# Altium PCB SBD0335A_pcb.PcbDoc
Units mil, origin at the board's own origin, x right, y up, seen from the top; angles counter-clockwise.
Board outline 1150 x 1150 mil, 2 copper layers (Top Layer, Bottom Layer), stack 64.8 mil thick; 36 components, 19 nets, 72 pads, 19 vias.
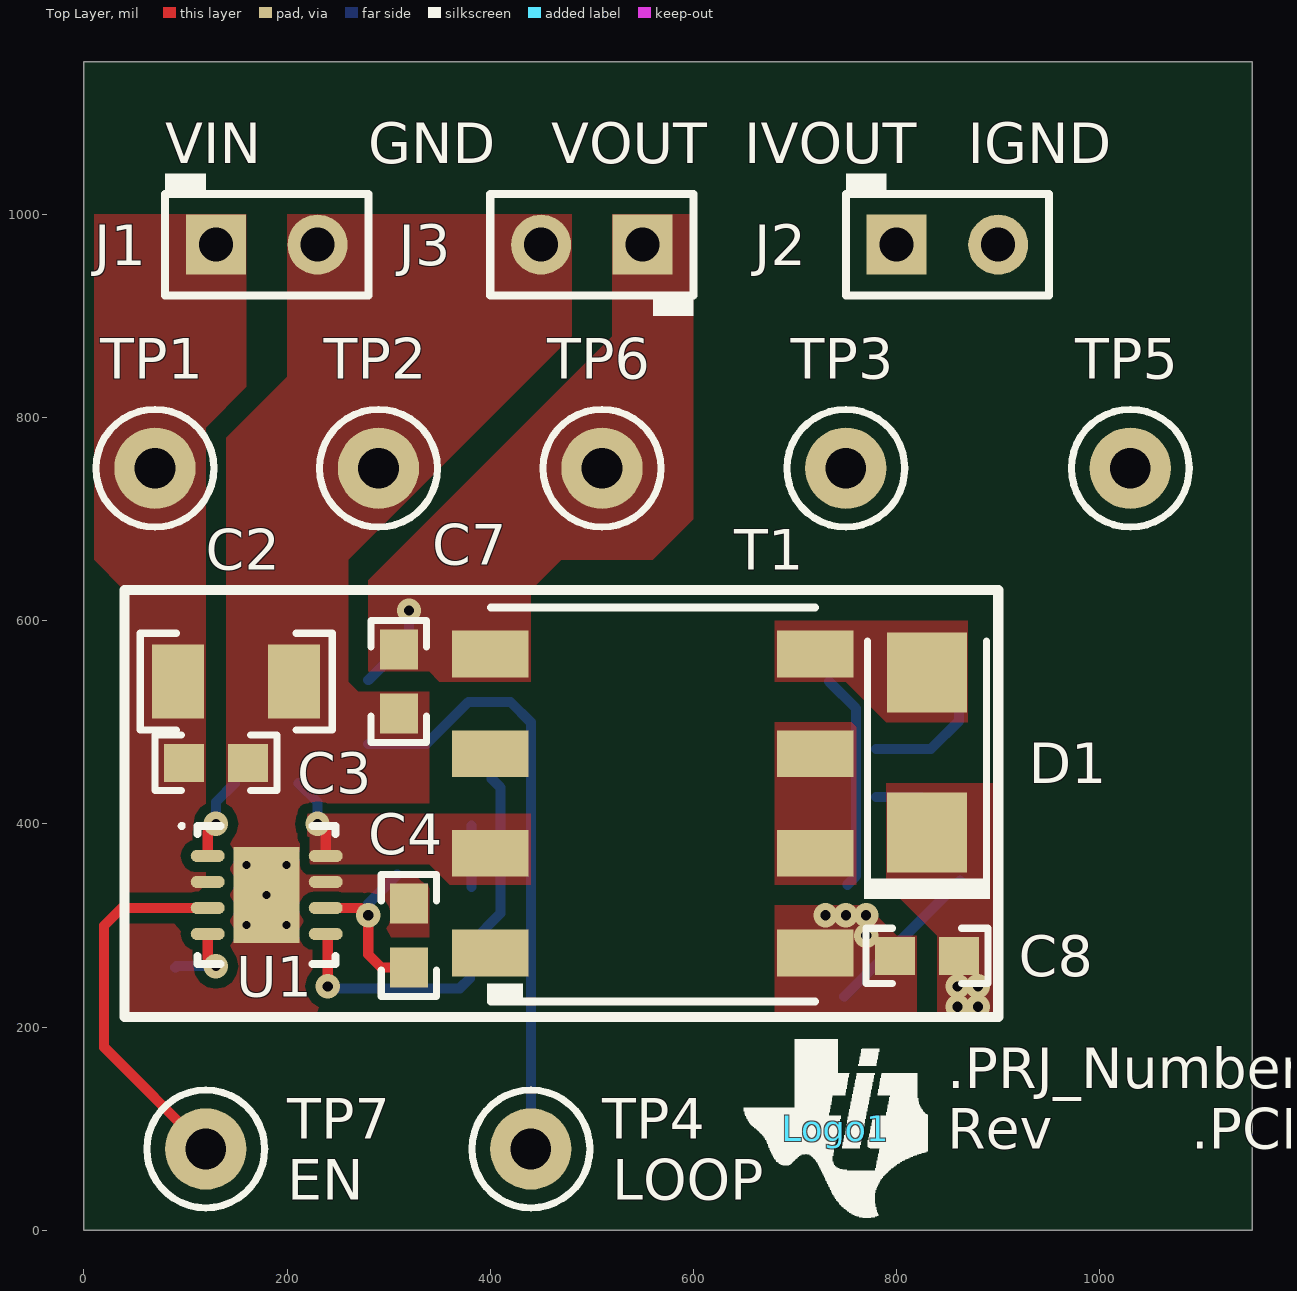
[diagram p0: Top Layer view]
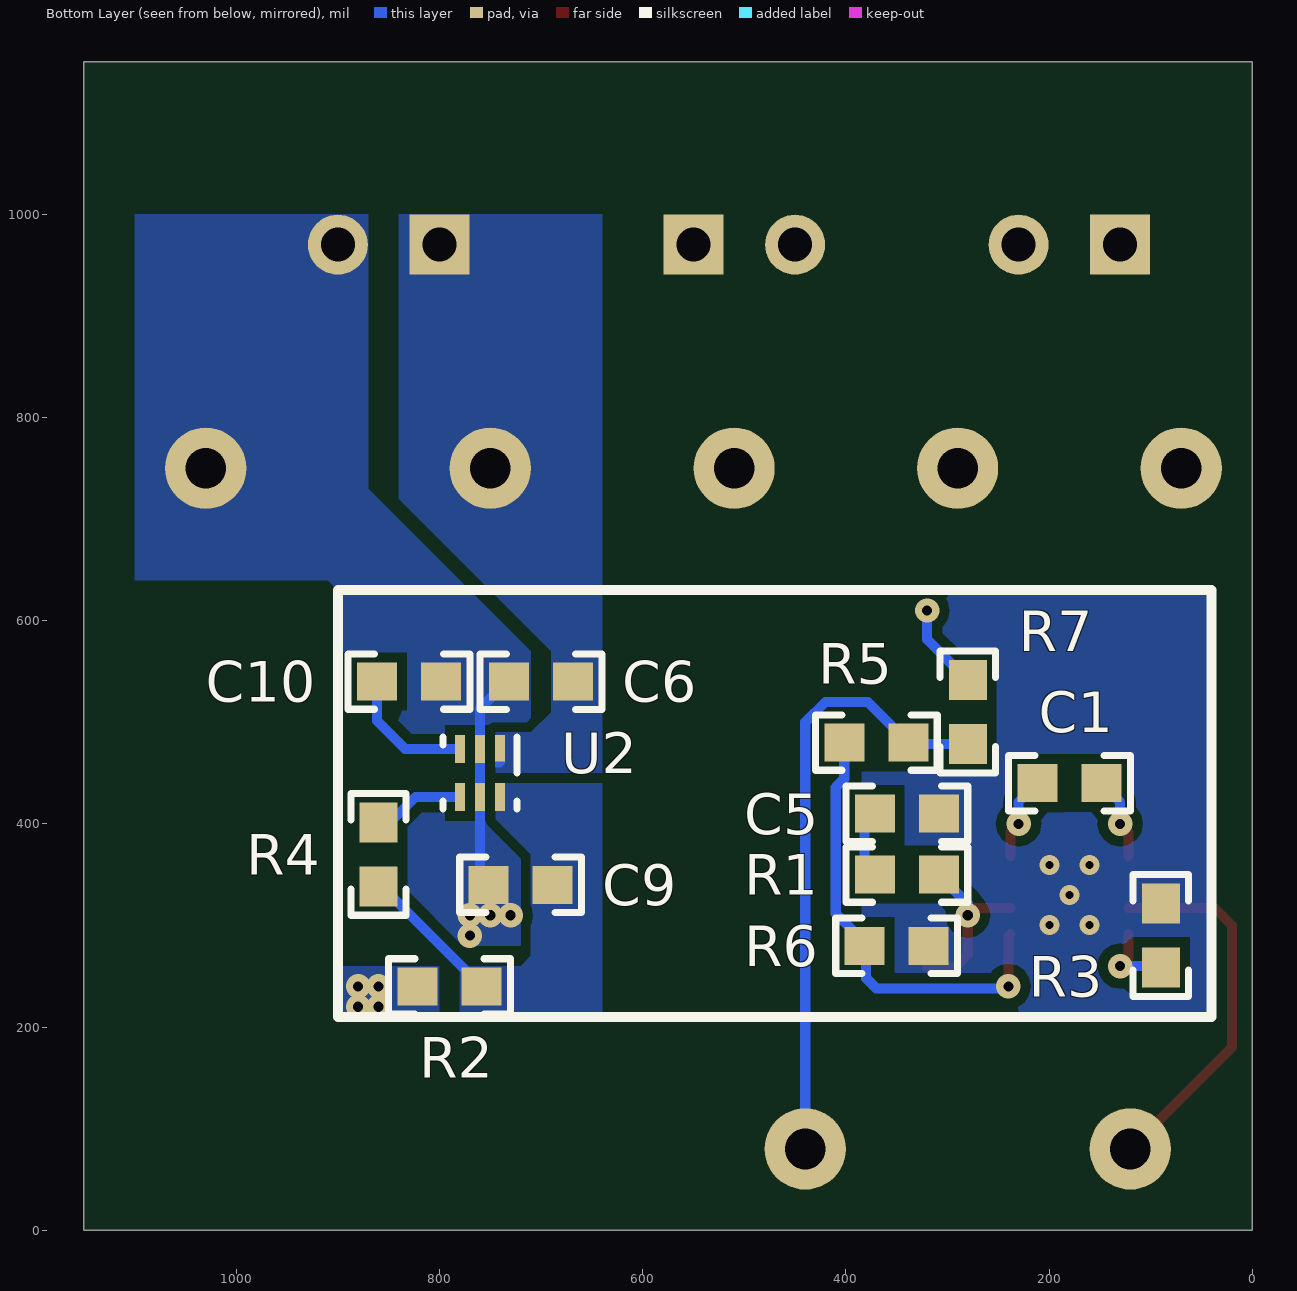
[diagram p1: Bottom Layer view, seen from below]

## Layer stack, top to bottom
Top Solder: solder mask 0.4, Solder Resist, Dk 3.5
Top Layer: signal copper 2.8
Dielectric1: core 59.2, FR-4, Dk 4.8
Bottom Layer: signal copper 2.8
Bottom Solder: solder mask 0.4, Solder Resist, Dk 3.5

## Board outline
0,0 0,1150 1150,1150 1150,0

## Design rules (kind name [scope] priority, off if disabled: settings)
AcuteAngle [All] p1: minimum=4.50000000000000E+0001 checktracksonly=FALSE
AssemblyTestPointUsage [All] p1: valid=2
Clearance Clearance_BoardEdge_MountingHoles [OnCopper and InComponentClass('Mounting Holes') vs IsKeepOut] p1: gap=40
Clearance Clearance_BoardEdge_Poly [OnCopper and InPoly vs IsKeepOut] p2: gap=25
Clearance Clearance_BoardEdge [OnCopper and Not InComponentClass('Logo') and not InComponentClass('FiducialMark') and not InRegion(1000,500,4000,800) and Not IsKeepout vs IsKeepOut] p3: gap=75
Clearance Clearance_Poly [InPolygon] p4: gap=10
Clearance [All] p5: gap=8
ComponentClearance ComponentClearance_Shunt [InComponentClass('Header') vs InComponentClass('Shunt')] p1: gap=0 collisioncheckmode=3 verticalgap=0 showdistances=FALSE
ComponentClearance ComponentClearance_Logo [InComponentClass('Logo')] p2: gap=50 collisioncheckmode=3 verticalgap=10 showdistances=FALSE
ComponentClearance ComponentClearance_ScrewToNut [(HasFootprint('NY PMS 440 0025 PH')) vs (HasFootprint('Keystone_1902C'))] p3: gap=5 collisioncheckmode=3 verticalgap=10 showdistances=FALSE
ComponentClearance ComponentClearance_MountingHoles [InComponentClass('Mounting Holes')] p4: gap=250 collisioncheckmode=3 verticalgap=100000 showdistances=FALSE
ComponentClearance ComponentClearance_SmallPassives [HasFootprint('0201*') or HasFootprint('0402*') or HasFootprint('0508') or HasFootprint('0603*') or HasFootprint('0612') or HasFootprint('0805*') or HasFootprint('0815*') or HasFootprint('0830*') or HasFootprint('1206*') or HasFootprint('1210*') or HasFootprint('1808*') or HasFootprint('1812*') or HasFootprint('1825*') or HasFootprint('2010*') or HasFootprint('2220*') or HasFootprint('2225*') or HasFootprint('2512*') or HasFootprint('2728*') or HasFootprint('3518*') vs HasFootprint('0201*') or HasFootprint('0402*') or HasFootprint('0508') or HasFootprint('0603*') or HasFootprint('0612') or HasFootprint('0805*') or HasFootprint('0815*') or HasFootprint('0830*') or HasFootprint('1206*') or HasFootprint('1210*') or HasFootprint('1808*') or HasFootprint('1812*') or HasFootprint('1825*') or HasFootprint('2010*') or HasFootprint('2220*') or HasFootprint('2225*') or HasFootprint('2512*') or HasFootprint('2728*') or HasFootprint('3518*')] p5: gap=20 collisioncheckmode=3 verticalgap=10 showdistances=FALSE
ComponentClearance ComponentClearance_THtoSMT [IsThruComponent vs IsSMTComponent] p6: gap=100 collisioncheckmode=3 verticalgap=30 showdistances=FALSE
ComponentClearance ComponentClearance_THtoTH [IsThruComponent vs IsThruComponent] p7: gap=118.11 collisioncheckmode=3 verticalgap=30 showdistances=FALSE
ComponentClearance [All] p8: gap=40 collisioncheckmode=3 verticalgap=10 showdistances=FALSE
DiffPairsRouting [All] p1: maxlimit=100 minlimit=10 mostfreqgap=10 toplayer_minwidth=15 toplayer_maxwidth=15 toplayer_prefwidth=15 bottomlayer_minwidth=15 bottomlayer_maxwidth=15 bottomlayer_prefwidth=15 maxuncoupledlength=1000
FabricationTestPointUsage TestPointUsage [All] p1: valid=2 allowmultiple=FALSE
FabricationTestpoint Testpoint [All] p1: side=3 testpointundercomponent=TRUE minsize=40 maxsize=100 preferedsize=60 minholesize=0 maxholesize=40 preferedholesize=32 testpointgrid=1 allowsidetop=TRUE allowsidebottom=TRUE usegrid=TRUE gridtolerance=0.01
FanoutControl Fanout_LCC [IsLCC] p1: bgadir=Out bgaviamode=Centered fanoutstyle=Auto fanoutdirection=Alternating viagrid=1 // Fanout_LCC (Default Rule)
FanoutControl Fanout_BGA [IsBGA] p2: bgadir=Out bgaviamode=Centered fanoutstyle=Auto fanoutdirection=Alternating viagrid=1 // Fanout_BGA (Default Rule)
FanoutControl Fanout_Default [All] p4: bgadir=Out bgaviamode=Centered fanoutstyle=Auto fanoutdirection=Alternating viagrid=1 // Fanout_Default (Default Rule)
FanoutControl Fanout_Small [(CompPinCount < 5)] p5: bgadir=Out bgaviamode=Centered fanoutstyle=Auto fanoutdirection=OutThenIn viagrid=1 // Fanout_Small (Default Rule)
HoleSize [All] p1: absolutevalues=TRUE maxlimit=251 minlimit=7 maxpercent=80.000 minpercent=20.000
MinimumAnnularRing MinimumAnnularRing_ThermalPadVias [IsVia and InAnyComponent] p1: minimumring=5
MinimumAnnularRing [All] p2: minimumring=5
MinimumSolderMaskSliver MinimumSolderMaskSliver_Logo [InComponentClass('Logo') vs InComponentClass('Logo')] p1: minsoldermaskwidth=0.7
MinimumSolderMaskSliver [All] p2: minsoldermaskwidth=3.94
PlaneConnect [All] p1: planeconnectstyle=Direct reliefexpansion=10 reliefentries=4 reliefconductorwidth=10 reliefairgap=10
PolygonConnect [All] p1: connectstyle=Direct reliefconductorwidth=10 reliefentries=4 polygonreliefangle="90 Angle" airgapwidth=10
RoutingVias ThermalPadVias [IsVia and InAnyComponent] p1: holewidth=7.87 width=19.68 viastyle="Through Hole" minholewidth=7 minwidth=19.68 maxholewidth=12.99 maxwidth=23.62
RoutingVias [All] p2: holewidth=16 width=34 viastyle="Through Hole" minholewidth=7 minwidth=18 maxholewidth=40 maxwidth=65
SMDToCorner [All] p1: distance=30000
SilkToSilkClearance [All] p1: silktosilkclearance=5
SilkToSolderMaskClearance SilkscreenOverComponentPads [IsPad] p1: minsilkscreentomaskgap=5 clearancetoexposedcopper=TRUE
SolderMaskExpansion [All] p1: expansion=1.97
UnpouredPolygon [All] p1: allowunpoured=FALSE
Width [All] p1: maxlimit=100 minlimit=6 preferedwidth=10 checkconnectedcopper=TRUE
15 further rules are at their usual default settings.

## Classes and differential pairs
component class SBD0335A_sch: C1 C2 C3 C4 C5 C6 C7 C8 C9 C10 D1 J1 J2 J3 R1 R2 R3 R4 R5 R6 T1 TP1 TP2 TP3 TP4 TP5 TP6 TP7 U1 U2
component class AssemblyNote: ZZ1 ZZ2 ZZ3 ZZ4
component class SBD0335A_hdw: Logo1 ZZ1 ZZ2 ZZ3 ZZ4
component class Logo: Logo1

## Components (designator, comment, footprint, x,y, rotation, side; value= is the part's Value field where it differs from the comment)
C1 "GRM188R71C103KA01D" 0603 180,440 r180 bottom
C2 "GRM31CR72A105KA01L" 1206 150,540 r0 top
C3 "GRM188R72A104KA35D" 0603 130,460 r0 top
C4 "GRM1885C1E102JA01D" 0603 320,290 r90 top
C5 "GRM188R71A474KA61D" 0603 340,410 r180 bottom
C6 "GRM188R71A105KA61D" 0603 700,540 r0 bottom
C7 "GRM188R71A225KE15D" 0603 310,540 r270 top
C8 "GRM188R71A225KE15D" 0603 830,270 r180 top
C9 "GRM188R71A225KE15D" 0603 720,340 r0 bottom
C10 "GRM188R70J104KA01D" 0603 830,540 r180 bottom
D1 "MBRA160T3G" SMA 830,470 r90 top
J1 "800-10-002-10-001000" Mill-Max_800-10-002-10-001000 180,970 r0 top
J2 "800-10-002-10-001000" Mill-Max_800-10-002-10-001000 850,970 r0 top
J3 "800-10-002-10-001000" Mill-Max_800-10-002-10-001000 500,970 r180 top
Logo1 "Texas Instruments" TI_Symbol_Overlay_Small 740,100 r0 top
R1 "CRCW060327K4FKEA" 0603 340,350 r180 bottom
R2 "CRCW06030000Z0EA" 0603 790,240 r0 bottom
R3 "CRCW06031M18FKEA" 0603 90,290 r270 bottom
R4 "CRCW06030000Z0EA" 0603 860,370 r270 bottom
R5 "CRCW0603316KFKEA" 0603 370,480 r0 bottom
R6 "CRCW0603100KFKEA" 0603 350,280 r0 bottom
R7 "CRCW060349R9FKEA" 0603 280,510 r270 bottom
T1 "TBD" Wurth_750314445 560,420 r90 top
TP1 "5000" Keystone5000 70,750 r0 top
TP2 "5001" Keystone5001 290,750 r0 top
TP3 "5000" Keystone5000 750,750 r0 top
TP4 "5002" Keystone5002 440,80 r0 top
TP5 "5001" Keystone5001 1030,750 r0 top
TP6 "5000" Keystone5000 510,750 r0 top
TP7 "5002" Keystone5002 120,80 r0 top
U1 "TPS54062DRBT" DRB0008B 180,330 r0 top
U2 "TPS71733DSE" DSE0006A 760,450 r270 bottom
ZZ1 "This Assembly Note is for PCB labels only" AssemblyNoteLabel 185,3938 r0 top
ZZ2 "These assemblies are ESD sensitive, ESD precautions shall be observed." AssemblyNote 185,3829.11 r0 top
ZZ3 "These assemblies must be clean and free from flux and all contaminants. Use of no clean flux is not acceptable." AssemblyNote 185,3740.56 r0 top
ZZ4 "These assemblies must comply with workmanship standards IPC-A-610 Class 2, unless otherwise specified." AssemblyNote 185,3652 r0 top

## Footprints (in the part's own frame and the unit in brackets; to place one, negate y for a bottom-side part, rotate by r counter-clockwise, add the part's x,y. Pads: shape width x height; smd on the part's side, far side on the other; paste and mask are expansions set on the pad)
0603 [mm] "0603 from SM-752 data"
  rect 1x0.95 smd: 1(-0.8,0) 2(0.8,0)
  silkscreen extent -1.52,-0.69 1.52,0.69, body extent -0.87,-0.47 0.87,0.47, height 0.85
1206 [mm] "1206 from SM-752 data"
  rect 1.3x1.85 smd: 1(-1.45,0) 2(1.45,0)
  silkscreen extent -2.4,-1.21 2.4,1.21, body extent -1.7,-0.9 1.7,0.9, height 1.35
AssemblyNote [mil] "Assembly Note"
AssemblyNoteLabel [mil] "Assembly Note for PCB Labels"
DRB0008B [mm] "SON, 8-Leads, Body 3x3mm, Pitch 0.65mm, Thermal Pad 2.4x1.65mm, TI Recommended"
  oval 0.85x0.3 smd paste-0.025 mask+0.07: 1(-1.475,0.975) 2(-1.475,0.325) 3(-1.475,-0.325) 4(-1.475,-0.975) 5(1.475,-0.975) 6(1.475,-0.325) 7(1.475,0.325) 8(1.475,0.975)
  rect 1.65x2.4 smd paste-0.825 mask+0.07: 9(0,0)
  silkscreen extent -2.17,-1.73 1.73,1.77, body extent -1.57,-1.57 1.58,1.58, height 1
DSE0006A [mm] "TI recommended land pattern"
  rect 0.66x0.25 smd: 1(-0.62,0.5)
  rect 0.7x0.25 smd: 2(-0.6,0) 3(-0.6,-0.5) 4(0.6,-0.5) 5(0.6,0) 6(0.6,0.5)
  Top Layer region: -0.3,0.625 -0.25,0.625 -0.15,0.525 -0.15,0.375 -0.3,0.375
  silkscreen extent -0.9,-0.92 0.9,0.92, body extent -0.77,-0.77 0.77,0.77, height 0.8
Keystone5000 [mil] "For Keystone 500x miniature loop terminals"
  round 80 hole 40: 1(0,0)
  silkscreen extent -58,-58 58,58, body extent -49,-49 49,49, height 182
Keystone5001 [mil] "For Keystone 500x miniature loop terminals"
  round 80 hole 40: 1(0,0)
  silkscreen extent -58,-58 58,58, body extent -49,-49 49,49, height 182
Keystone5002 [mil] "For Keystone 500x miniature loop terminals"
  round 80 hole 40: 1(0,0)
  silkscreen extent -58,-58 58,58, body extent -49,-49 49,49, height 182
Mill-Max_800-10-002-10-001000 [mm] "Mill-Max"
  rect 1.5x1.5 hole 0.85: 1(-1.27,0)
  round 1.5 hole 0.85: 2(1.27,0)
  silkscreen extent -2.54,-1.27 2.54,1.78, body extent -2.54,-1.27 2.54,1.27, height 8.13
SMA [mm] "Molded Diode, 2-Leads, Body 4.3x2.6mm, IPC Medium Density, based on OnSemi component dimensions and land pattern"
  rect 2x2 smd: 1(-2,0) 2(2,0)
  silkscreen extent -3.66,-1.57 2.79,1.57, body extent -2.6,-1.3 2.6,1.3, height 2.42
TI_Symbol_Overlay_Small [mil]
  silkscreen extent -90,-88 91,88
Wurth_750314445 [mm] "WURTH"
  rect 1.17x1.91 smd: 1(-3.735,4.065) 2(-1.245,4.065) 3(1.245,4.065) 4(3.735,4.065) 5(3.735,-4.065) 6(1.245,-4.065) 7(-1.245,-4.065) 8(-3.735,-4.065)
  silkscreen extent -5,-4.05 4.9,4.15, body extent -4.92,-4.58 4.9,4.58, height 10.1

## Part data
C1: "CAP, CERM, 0.01uF, 16V, +/-10%, X7R, 0603"
C2: "CAP, CERM, 1uF, 100V, +/-10%, X7R, 1206"
C3: "CAP, CERM, 0.1uF, 100V, +/-10%, X7R, 0603"
C4: "CAP, CERM, 1000pF, 25V, +/-5%, C0G/NP0, 0603"
C5: "CAP, CERM, 0.47uF, 10V, +/-10%, X7R, 0603"
C6: "CAP, CERM, 1uF, 10V, +/-10%, X7R, 0603"
C7 C8 C9: "CAP, CERM, 2.2uF, 10V, +/-10%, X7R, 0603"
C10: "CAP, CERM, 0.1uF, 6.3V, +/-10%, X7R, 0603"
D1: "Diode, Schottky, 60V, 1A, SMA"
J1 J2 J3: "Header, 2x1, 100mil, SMT"
Logo1: library part TI_Logo, "Texas Instrument Corporate Signature"
R1: "RES, 27.4k ohm, 1%, 0.1W, 0603"
R2 R4: "RES, 0 ohm, 5%, 0.1W, 0603"
R3: "RES, 1.18Meg ohm, 1%, 0.1W, 0603"
R5: "RES, 316k ohm, 1%, 0.1W, 0603"
R6: "RES, 100k ohm, 1%, 0.1W, 0603"
R7: "RES, 49.9 ohm, 1%, 0.1W, 0603"
T1: library part XFMR_750311880, "Transformer, ±10%"
TP1 TP3 TP6: "Test Point, Miniature, Red, TH"
TP2 TP5: "Test Point, Miniature, Black, TH"
TP4 TP7: "Test Point, Miniature, White, TH"
U1: "Buck Step Down Regulator with 4.7 to 60 V Input and 0.8 to 58 V Output, -40 to 125 degC, 8-Pin SON (DRB), Green (RoHS & no Sb/Br)"
U2: "Low Noise, High-Bandwidth PSRR Low-Dropout 150mA Linear Regulator, DSE0006A"
ZZ1: library part AssemblyNoteLabel
ZZ2 ZZ3 ZZ4: library part AssemblyNote

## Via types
v1: diameter 24, hole 10, Top Layer to Bottom Layer, tented both sides, 14 vias
v2: diameter 19.68, hole 7.87, Top Layer to Bottom Layer, 5 vias

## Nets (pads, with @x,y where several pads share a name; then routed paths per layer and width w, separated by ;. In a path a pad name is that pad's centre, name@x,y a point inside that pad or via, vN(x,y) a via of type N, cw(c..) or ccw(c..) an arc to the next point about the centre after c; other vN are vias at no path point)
GND: C2.2 C3.2 C4.2 C5.2 C7.2 J1.2 J3.2 R3.1 R6.1 TP2.1 U1.7 U1.9
  other v2: 160.32,300.47 199.68,300.47 180,330 160.32,359.53 199.68,359.53
ISOGND: C6.2 C8.2 C9.2 C10.2 J2.2 T1.8 TP5.1 U2.2 U2.5 | length 214.4
  Bottom Layer w10: C6.2@733.62,540 760,513.62 U2.2 U2.5 760,348.5 C9.2
  other v1: 770.02,290 730,310 750,310 770,310
NetC1_1: C1.1 T1.2 U1.8 | length 82.6
  Top Layer w10: v1(230,400) 238.07,391.93 U1.8
  Bottom Layer w10: C1.1 230,421.5 v1(230,400)
NetC1_2: C1.2 U1.1 | length 82.6
  Top Layer w10: U1.1 121.93,391.93 v1(130,400)
  Bottom Layer w10: v1(130,400) 130,421.5 C1.2
NetC2_1: C2.1 C3.1 J1.1 TP1.1 U1.2
NetC4_1: C4.1 R1.2 U1.6 | length 180.6
  Top Layer w10: U1.6 272.8,317.2 v1(280,310) 280,271.46 292.95,258.5 C4.1
  Bottom Layer w10: v1(280,310) 280,321.5 R1.2
NetC5_1: C5.1 R1.1 | length 60
  Bottom Layer w10: R1.1@381.5,338.05 C5.1@381.5,398.05
NetC6_1: C6.1 J2.1 TP3.1 U2.1
NetC7_1: C7.1 J3.1 R7.1 T1.4 TP6.1 | length 85.1
  Bottom Layer w10: R7.1 320,581.5 v1(320,610)
NetC8_1: C8.1 D1.1 R2.2
  other v1: 860,220 880,220 860,240 880,240
NetC9_1: C9.1 R2.1 R4.2 U2.6 | length 161.1
  Bottom Layer w10: R2.1@748.5,230 R4.2@862.44,343.94
NetC10_1: C10.1 U2.3 | length 131.9
  Bottom Layer w10: U2.3 833.62,473.62 861.5,501.5 C10.1
NetD1_2: D1.2 T1.5
NetR3_2: R3.2 U1.4 | length 75.6
  Top Layer w10: U1.4 121.93,268.07 v1(130,260)
  Bottom Layer w10: R3.2 91.5,260 v1(130,260)
NetR4_1: R4.1 U2.4 | length 95.4
  Bottom Layer w10: U2.4 823.62,426.38 R4.1@860,390
NetR5_1: R5.1 R7.2 TP4.1 | length 613.4
  Bottom Layer w10: R7.2 R5.1@337.01,478.5 ; R5.1 378.5,520 420,520 440,500 440,210 TP4.1@440,70
NetR5_2: R5.2 R6.2 U1.5 | length 440.4
  Top Layer w10: U1.5 240,289.69 v1(240,240)
  Bottom Layer w10: v1@240,238.05 370,238.05 380,248.05 R6.2@380,276.56 ; R6.2 381.5,283.23 410,311.73 410,435.88 401.5,444.39 R5.2
NetT1_6: T1.6 T1.7
NetTP7_1: TP7.1 U1.3 | length 370.5
  Top Layer w10: TP7.1 20,180 20,300 37.2,317.2 U1.3
pads on no net: T1.1 T1.3

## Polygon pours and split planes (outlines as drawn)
NetT1_6 on Top Layer "Top Layer-T6toT7" (solid, remove dead copper, pour order 17): 680,500 760,500 760,340 680,340
NetC2_1 on Top Layer "Top Layer-VIN" (solid, pour order 16): 10,1000 10,660 40,630 40,318.05 120.01,318.05 119.99,789.99 160,830 160,1000
GND on Top Layer "Top Layer-GND" (solid, remove dead copper, pour order 22): 40,210 40,310 140,310 140,780 200,840 200,1000 480,1000 480,880 260,660 260,540 270,530 340,530 340,210
NetD1_2 on Top Layer "Top Layer-ISOSW" (solid, remove dead copper, pour order 15): 680,600 870,600 870,500 790,500 750,540 680,540
NetC8_1 on Top Layer "Top Layer-VISO" (solid, remove dead copper, pour order 21): 790,440 900,440 900,210 840,210 840,290 790,340
ISOGND on Top Layer "Top Layer-ISOGND" (solid, remove dead copper, pour order 19): 680,320 680,210 820,210 820,290 800,290 770,320
NetC7_1 on Top Layer "Top Layer-VOUT" (solid, remove dead copper, pour order 20): 280,550 340,550 350,540 440,540 440,630 470,660 560,660 600,700 600,1000 520,1000 520,880 280,640
NetC1_1 on Top Layer "Top Layer-PH" (solid, remove dead copper, pour order 18): 220,360 340,360 360,340 440,340 440,410 220,410
GND on Bottom Layer "Bottom Layer-GND" (solid, remove dead copper, pour order 14): 40,630 40,210 384.45,210 384.45,630
NetC8_1 on Bottom Layer "Bottom Layer-ISOSWOUT" (solid, remove dead copper, pour order 23): 800,260 900,260 900,210 800,210
NetC9_1 on Bottom Layer "Bottom Layer-LDOIN" (solid, remove dead copper, pour order 24): 780,260 720,260 710,270 710,370 750,410 750,440 640,440 640,210 780,210
NetC6_1 on Bottom Layer "Bottom Layer-VISO" (solid, remove dead copper, pour order 25): 750,450 640,450 640,1000 840,1000 840,720 690,570 690,510 710,490 750,490
ISOGND on Bottom Layer "Bottom Layer-ISOGND" (solid, remove dead copper, pour order 26): 870,1000 870,730 710,570 710,280 900,280 900,630 910,640 1100,640 1100,1000

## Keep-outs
Keep-Out Layer:
  text ".Layer_Name" at 577,-858.49 h60

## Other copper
Top Layer:
  text ".Layer_Name" at 577,-858.49 h60
Bottom Layer:
  text ".Layer_Name" at 577,-858.49 h60

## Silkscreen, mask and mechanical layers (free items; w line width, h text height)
Top Overlay:
  lines w10: 40,210 900,210 900,630 40,630 40,210
  text "VIN" at 80,1050 h40
  text "GND" at 280,1050 h40
  text "VOUT" at 460,1050 h40
  text "IVOUT" at 650,1050 h40
  text "IGND" at 870,1050 h40
  text ".PRJ_Number" at 850,140 h40
  text "Rev" at 850,80 h40
  text ".PCB_Rev" at 1090,80 h40
  text "EN" at 200,30 h40
  text "LOOP" at 520,30 h40
  text ".Layer_Name" at 577,-858.49 h60
Bottom Overlay:
  lines w10: 40,210 40,630 900,630 900,210 40,210
  text ".Layer_Name" at 577,-858.49 h60
Top Paste:
  text ".Layer_Name" at 577,-858.49 h60
Bottom Paste:
  text ".Layer_Name" at 577,-858.49 h60
Top Solder:
  text ".Layer_Name" at 577,-858.49 h60
  text ".Layer_Name" at 577,-858.49 h60
Bottom Solder:
  text ".Layer_Name" at 577,-858.49 h60
Drill Guide:
  text ".Layer_Name" at 577,-858.49 h60
M1 Board Outline:
  the board outline again, w10
  text ".Layer_Name" at 577,-858.49 h60
M2 Board Dimensions:
  rectangle: 124.5,-410.5 499.5,-285.5
  rectangle: -0.5,-285.5 124.5,-160.5
  lines w7: -0.5,-285.5 999.5,-285.5 ; 124.5,-410.5 124.5,-160.5 ; 249.5,-410.5 249.5,-160.5 ; 499.5,-410.5 499.5,-160.5 ; 749.5,-410.5 749.5,-160.5 ; -0.5,-160.5 -0.5,-410.5 999.5,-410.5 999.5,-160.5 ; -0.5,-160.5 999.5,-160.5 ; -0.5,-160.5 999.5,-160.5
  lines w10: -0.5,-475.5 -0.5,-455.5 ; 59.5,-485.5 -0.5,-465.5 ; 59.5,-445.5 -0.5,-465.5 ; 223.58,-465.5 -0.5,-465.5 ; 775.42,-465.5 999.5,-465.5 ; 939.5,-485.5 999.5,-465.5 ; 939.5,-445.5 999.5,-465.5 ; 999.5,-475.5 999.5,-455.5
  text "1000 (mil)" at 233.58,-501.49 h60
  text ".Layer_Name" at 577,-858.49 h60
M3 3D STEP Top:
  text ".Layer_Name" at 577,-858.49 h60
M4 3D STEP Bottom:
  text ".Layer_Name" at 577,-858.49 h60
M5 Assembly Top:
  lines w10: -292,-930.17 6308,-930.17 ; -292,-726.83 6310,-726.83 ; -292,-523.5 -292,-1133.5 3713,-1133.5 6310,-1133.5 6310,-523.5 -291.5,-523.5 -291.5,-1133.5 1284,-1133.5 ; 2173,-1133.5 2173,-523.5 ; 3440,-726.83 3440,-523.5 ; 4280,-726.83 4280,-523.5 ; 4902,-1140 4902,-937.17
  text "COMPONENTS MARKED 'DNP' SHOULD NOT BE POPULATED." at 1153.5,-318.5 h60
  text "ASSEMBLY VARIANT:" at 1153,-434 h60
  text ".VariantName" at 2189,-434 h60
  text "PCB VIEWED FROM TOP SIDE" at -228.5,-655.67 h60
  text "BOARD #:" at 2248,-655.67 h60
  text ".PRJ_Number" at 2793.5,-655.67 h60
  text "REV:" at 3638,-655.67 h60
  text ".PCB_Rev" at 3929.5,-655.67 h60
  text "SVN REV:" at 4476,-655.67 h60
  text ".VersionControl_RevNumber" at 4982,-655.67 h60
  text "IGNORE ->" at -228.5,-858.49 h60
  text "PLOT NAME =" at -228.5,-1064.34 h60
  text ".plot_File_Name" at 577,-1064.34 h60
  text "GENERATED    :" at 2250,-1064.34 h60
  text ".Print_Date" at 3119.5,-1064.34 h60
  text ".Print_Time" at 3848.5,-1064.34 h60
  text "TEXAS INSTRUMENTS" at 5113,-1064.34 h60
M6 Assembly Bottom:
  lines w10: -292.5,-727.33 6309.5,-727.33 ; -290.5,-930.67 6309.5,-930.67 ; 1115.5,-1140.5 1115.5,-937.67 ; 1737.5,-727.33 1737.5,-524 ; 2577.5,-727.33 2577.5,-524 ; 3844.5,-1134 3844.5,-524 ; 4733.5,-1134 6309,-1134 6309,-524 -292.5,-524 -292.5,-1134 2304.5,-1134 6309.5,-1134 6309.5,-524
  text "COMPONENTS MARKED 'DNP' SHOULD NOT BE POPULATED." at 6102,-318 h60
  text ".VariantName" at 5058,-434 h60
  text "ASSEMBLY VARIANT:" at 6097,-434 h60
  text ".VersionControl_RevNumber" at 1035.5,-656.17 h60
  text "SVN REV:" at 1541.5,-656.17 h60
  text ".PCB_Rev" at 2088,-656.17 h60
  text "REV:" at 2379.5,-656.17 h60
  text ".PRJ_Number" at 3224,-656.17 h60
  text "BOARD #:" at 3769.5,-656.17 h60
  text "PCB VIEWED FROM BOTTOM SIDE" at 6246,-656.17 h60
  text "IGNORE ->" at 2547.85,-858.49 h60
  text "TEXAS INSTRUMENTS" at 904.5,-1064.84 h60
  text ".Print_Time" at 2169,-1064.84 h60
  text ".Print_Date" at 2898,-1064.84 h60
  text "GENERATED    :" at 3767.5,-1064.84 h60
  text ".plot_File_Name" at 5440.5,-1064.84 h60
  text "PLOT NAME =" at 6246,-1064.84 h60
M9 Title Sheet:
  drawing of 57 lines, arcs and shapes, not listed
  text "1" at 739.84,8036.5 h70
  text "2" at 3235.5,8036.5 h70
  text "3" at 5724.84,8036.5 h70
  text "4" at 8231.51,8036.5 h70
  text "5" at 10730.5,8036.5 h70
  text "6" at 13235.5,8036.5 h70
  text "A" at -416.5,6893.5 h70
  text "A" at 14383.5,6893.5 h70
  text "B" at -416.5,4513.5 h70
  text "B" at 14383.5,4513.5 h70
  text "C" at -416.5,2138.5 h70
  text "C" at 14383.5,2138.5 h70
  text "PROJECT TITLE:" at 11343.5,277.5 h45
  text ".PRJ_Title" at 11393.5,144.17 h70
  text "DESIGNED FOR:" at 11343.5,-23.5 h45
  text ".PRJ_Customer" at 11393.5,-163.5 h70
  text "D" at -416.5,-231.5 h70
  text "D" at 14383.5,-231.5 h70
  text "FILE NAME:" at 11343.5,-323.5 h45
  text ".PCB_File_Name_No_Path" at 11393.5,-443.5 h70
  text "Texas Instruments (TI) and/or its licensors do not warrant the accuracy or completeness of this specification" at 6374,-605.34 h45
  text "ENGINEER:" at 11343.5,-613.5 h45
  text "LAYOUT BY:" at 12848.5,-613.5 h45
  text "or any information contained therein. TI and/or its licensors do not warrant that this design will meet" at 6329.01,-718 h45
  text ".PRJ_Engineer" at 11393.5,-768.49 h70
  text ".PCB_Layout" at 12899,-768.49 h70
  text "the specifications, will be suitable for your application or fit for any particular purpose, or will operate in" at 6329.01,-830.67 h45
  text ".Layer_Name" at 577,-858.49 h60
  text "ALTIUM DESIGNER VERSION:" at 12848.5,-923.5 h45
  text "an implementation. TI and/or its licensors do not warrant that the design is production worthy. You should" at 6329.01,-943.33 h45
  text "completely validate and test your design implementation to confirm the system functionality for your application." at 6374,-1056 h45
  text ".print_Scale" at 11393.5,-1056.83 h70
  text ".Application_BuildNumber" at 12899,-1056.83 h70
  text "1" at 739.84,-1263.5 h70
  text "2" at 3235.5,-1263.5 h70
  text "3" at 5724.84,-1263.5 h70
  text "4" at 8231.51,-1263.5 h70
  text "5" at 10730.5,-1263.5 h70
  text "6" at 13235.5,-1263.5 h70
M10 Fab Notes:
  drawing of 212 lines, arcs and shapes, not listed
  text "DESIGN INFORMATION" at 12381.02,6810 h60
  text "(REFER ALSO ARRAY/PANEL PROFILING INFORMATION)" at 12019.46,6648.29 h60
  text "BOARD SIZE" at 11333.46,6644 h60
  text "1150MIL" at 11795.78,6516.18 h60
  text "X" at 12301.46,6516.18 h60
  text "1150MIL" at 12532.78,6516.18 h60
  text "Number of Layers :" at 11736.46,6319 h60
  text "2" at 12831.27,6309 h60
  text "MIN. TRACK WIDTH:" at 11736.46,6180 h60
  text "8" at 12832.7,6180 h60
  text "MIL" at 12987.46,6180 h60
  text "MIN. CLEARANCE:" at 11736.46,6048 h60
  text "8" at 12832.7,6048 h60
  text "MIL" at 12987.46,6048 h60
  text "MIN. VIA PAD SIZE:" at 11736.46,5916 h60
  text "24" at 12802.71,5916 h60
  text "MIL" at 12987.46,5916 h60
  text "0.05mm (2MIL)" at 12431.46,5774.29 h60
  text "MINIMUM ANNULAR RING" at 11407.23,5770 h60
  text "EXTERNAL" at 13139.46,5770 h60
  text "PER" at 11607.23,5652 h60
  text "IPC-D-275 CLASS 2 LEVEL C" at 11827.23,5652 h60
  text "MIL, HOLES" at 13315.46,5539.71 h60
  text "+/-" at 12923,5539 h60
  text "+/-" at 13777,5539 h60
  text "REGISTRATION TOLERANCES:" at 11407.23,5534 h60
  text "METAL" at 12607,5534 h60
  text "5" at 13183.2,5534 h60
  text "3" at 14016.2,5534 h60
  text "MIL" at 14132.46,5534 h60
  text "MATERIAL:" at 11332.46,5324.54 h60
  text "FR-4 High Tg" at 12318.9,5184.21 h60
  text "FR-408" at 11753.46,5175.64 h60
  text "X" at 12165.46,5175.64 h60
  text "OTHER" at 13241.46,5175.64 h60
  text "62 MIL (1.6mm) +/-10%" at 12073.56,5012.92 h60
  text "THICKNESS:" at 11407.23,5008.64 h60
  text "X" at 11945.4,5008.64 h60
  text "OTHER" at 13358.46,5008.64 h60
  text "TOLERANCE:" at 11407.23,4850.64 h60
  text "X" at 12246.53,4850.64 h60
  text "ANSI IPC-6012 TYPE 3 CLASS 2" at 12433.48,4850.64 h60
  text "OTHER +/-" at 12433.46,4694.64 h60
  text "BOW & TWIST:" at 11407.23,4537.64 h60
  text "X" at 12246.53,4537.64 h60
  text "ANSI IPC-6012 TYPE 3 CLASS 2" at 12433.48,4537.64 h60
  text "OTHER +/-" at 12433.46,4379.13 h60
  text "COPPER THICKNESS (FINISHED):" at 11332.46,4243.64 h60
  text "1.4MIL (1oz)" at 12212.46,4090.92 h60
  text "2MIL (1.4oz)" at 12979.46,4090.92 h60
  text "2.8MIL (2oz)" at 13706.46,4090.92 h60
  text "X" at 13580,4090 h60
  text "OUTER:" at 11689.46,4086.64 h60
  text "1.4MIL (1oz)" at 12212.46,3933.92 h60
  text "2.8MIL (2oz)" at 12979.46,3933.92 h60
  text "N/A" at 13706,3934.29 h60
  text "INNER SIGNAL:" at 11400.38,3929.64 h60
  text "X" at 13580,3930 h60
  text "DRILLING:" at 11332.46,3790.64 h60
  text "REFERENCE:" at 11407.23,3673.64 h60
  text "X" at 12055.46,3673.64 h60
  text "AS SHOWN" at 12242.46,3673.64 h60
  text "X" at 12956.46,3673.64 h60
  text "NC_DRILL FILES" at 13093.46,3673.64 h60
  text "PTH MIN COPPER THICKNESS:" at 11407.23,3515.64 h60
  text "X" at 12757.46,3515.64 h60
  text "1MIL" at 12894.46,3515.64 h60
  text "OTHER" at 13391.46,3515.64 h60
  text "BOARD FINISH:" at 11332.46,3356.64 h60
  text "SILKSCREEN:" at 11487.68,3238.64 h60
  text "X" at 12436.46,3238.64 h60
  text "TOP" at 12562.46,3238.64 h60
  text "X" at 12946.46,3238.64 h60
  text "BOTTOM" at 13073.46,3238.64 h60
  text "SILKSCREEN COLOR:" at 11487.68,3071.64 h60
  text "X" at 12435.42,3071.64 h60
  text "WHITE" at 12562.46,3071.64 h60
  text "OTHER" at 13073.46,3071.64 h60
  text "SOLDER RESIST COLOR:" at 11487.68,2901.64 h60
  text "X" at 12055.42,2742.44 h60
  text "GREEN" at 12182.46,2742.44 h60
  text "BLUE" at 12773.46,2742.44 h60
  text "OTHER" at 13311.46,2742.44 h60
  text "IMMERSION GOLD (ENIG)" at 12393.46,2553.92 h60
  text "ENEPIG" at 13731,2550.64 h60
  text "SURFACE FINISH:" at 11332.46,2549.64 h60
  text "IMM. TIN/SILVER OR EQUIV" at 11662,2392.64 h60
  text "OTHER" at 13093.46,2392.64 h60
  text "X" at 11500,2390 h60
  text "ARRAY/PANEL:" at 11332.46,2213.64 h60
  text "CUT AND TRIM PER MECH LAYER 1" at 12393.46,2209.35 h60
  text "N.C. ROUTE" at 12393.46,2057.64 h60
  text "X" at 13072.46,2057.64 h60
  text "V. SCORE" at 13259.46,2057.64 h60
  text "CERTIFICATION:" at 11332.46,1920.64 h60
  text "MATERIALS AND WORKMANSHIP FOR ALL PCBS" at 12057.46,1920.64 h60
  text "TO MEET OR EXCEED THE REQUIREMENTS OF:" at 12057.46,1822.64 h60
  text "X" at 11683.96,1686.13 h60
  text "ANSI IPC-A-600F CLASS ->" at 11822.96,1686.13 h60
  text "X" at 13462.02,1686.13 h60
  text "2" at 13580.96,1686.14 h60
  text "1" at 13265.96,1684.64 h60
  text "3" at 13934.96,1684.64 h60
  text "X" at 11686.02,1526.64 h60
  text "UL 94V-0" at 11822.96,1526.64 h60
  text "X" at 12498.02,1526.64 h60
  text "RoHS" at 12634.96,1526.64 h60
  text "OTHER" at 13279.36,1526.64 h60
  text "PER ORDER" at 13676.42,1526.64 h60
  text "ADDITIONAL REQUIREMENTS:" at 11332.46,1385.64 h60
  text "MICROSECTION:" at 11407.23,1270.64 h60
  text "YES" at 12312.96,1270.64 h60
  text "REQUIRED" at 13174.46,1114.49 h60
  text "BARE BOARD ELEC. TEST:" at 11407.23,1111.64 h60
  text "NONE" at 12712.96,1111.64 h60
  text "X" at 13047.46,1111.64 h60
  text "PER ORDER" at 13766.46,1111.64 h60
  text "MANUFACTURER'S UL:" at 11407.23,954.64 h60
  text "RAIL" at 12572.96,950.35 h60
  text "METAL" at 13064.77,950.35 h60
  text "X" at 13440,950 h60
  text "SILK" at 13576.46,950.35 h60
  text ".Layer_Name" at 577,-858.49 h60
M11 Gerber Information:
  lines w10: -292,-930.17 6308,-930.17 ; -292,-726.83 6310,-726.83 ; -292,-523.5 -292,-1133.5 3713,-1133.5 6310,-1133.5 6310,-523.5 -291.5,-523.5 -291.5,-1133.5 1284,-1133.5 ; 2173,-1133.5 2173,-523.5 ; 3440,-726.83 3440,-523.5 ; 4280,-726.83 4280,-523.5 ; 4902,-1140 4902,-937.17
  text "ALL ARTWORK VIEWED FROM TOP SIDE" at -228.5,-655.67 h60
  text "BOARD #:" at 2248,-655.67 h60
  text ".PRJ_Number" at 2793.5,-655.67 h60
  text "REV:" at 3638,-655.67 h60
  text ".PCB_Rev" at 3929.5,-655.67 h60
  text "SVN REV:" at 4476,-655.67 h60
  text ".VersionControl_RevNumber" at 4982,-655.67 h60
  text "LAYER NAME =" at -228.5,-858.49 h60
  text "PLOT NAME =" at -228.5,-1064.34 h60
  text ".plot_File_Name" at 577,-1064.34 h60
  text "GENERATED    :" at 2250,-1064.34 h60
  text ".Print_Date" at 3119.5,-1064.34 h60
  text ".Print_Time" at 3848.5,-1064.34 h60
  text "TEXAS INSTRUMENTS" at 5113,-1064.34 h60
M12 Stackup:
  lines w7: 11360,7626.83 14230,7626.83 ; 11360,7756.83 14230,7756.83 ; 11300,7032 ccw(c11342,7032) 11342,6990 14248,6990 ccw(c14248,7032) 14290,7032 14290,7898 ccw(c14248,7898) 14248,7940 11342,7940 ccw(c11342,7898) 11300,7898 11300,7032
  text "Layer Stack Up Detail for: SBD0335A_pcb.PcbDoc" at 11360,7803.12 h61
  text "Layer" at 11360,7708.33 h30
  text "Gerber" at 12372.44,7708.33 h30
  text "Copper" at 12979,7708.33 h30
  text "Dielectric" at 13634.55,7708.33 h30
  text "Name" at 11360,7648.33 h30
  text "Document" at 12372.44,7648.33 h30
  text "Thickness" at 12979,7648.33 h30
  text "Material" at 13634.55,7648.33 h30
  text "Top Solder Mask" at 11360,7534.27 h42
  text "(.GTS)" at 12372.44,7534.27 h42
  text "Solder Resist" at 13634.55,7534.27 h42
  text "Top Layer" at 11360,7415.52 h42
  text "(.GTL)" at 12372.44,7415.52 h42
  text "2.8mil" at 12979,7415.52 h42
  text "FR-4" at 13634.55,7356.15 h42
  text "Bottom Layer" at 11360,7296.77 h42
  text "(.GBL)" at 12372.44,7296.77 h42
  text "2.8mil" at 12979,7296.77 h42
  text "Bottom Solder Mask" at 11360,7178.02 h42
  text "(.GBS)" at 12372.44,7178.02 h42
  text "Solder Resist" at 13634.55,7178.02 h42
  text ".Layer_Name" at 577,-858.49 h60
M13 Component Bodies Top:
  text ".Layer_Name" at 577,-858.49 h60
M14 Component Bodies Bottom:
  text ".Layer_Name" at 577,-858.49 h60
M15 Courtyards Top:
  text ".Layer_Name" at 577,-858.49 h60
M16 Courtyards Bottom:
  text ".Layer_Name" at 577,-858.49 h60
Drill Drawing:
  text ".legend" at 5122.5,725.5 h60
  text "Drill Table" at 5147.5,540.5 h60
  text ".Layer_Name" at 577,-858.49 h60

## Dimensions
40,-10 to 900,-10 on M2 Board Dimensions
-10,210 to -10,630 on M2 Board Dimensions
0,1230 to 1150,1210 on M2 Board Dimensions
1168.02,0.06 to 1188.02,1150.06 on M2 Board Dimensions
